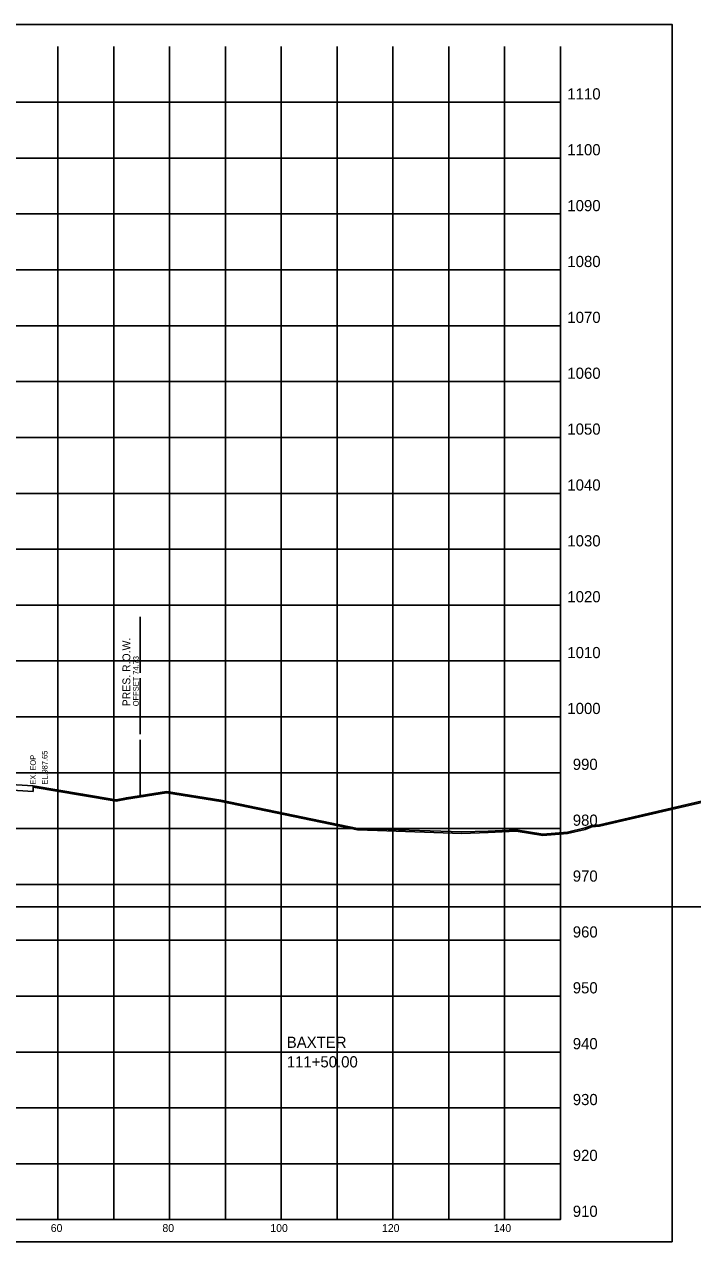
# Model space of a CAD drawing. Extents: x 5868 to 6683, y 2883 to 19120.
# Drawn here: x 6247.8 to 6367.5, y 14385.1 to 14603 of the extents above; entities that cross this region are included whole.
import ezdxf

# ---------------------------------------------------------------- set-up
doc = ezdxf.new("R2010")
doc.units = 0
for name, color, linetype in [('DESIGN - SHEET - Corner Text', 7, 'Continuous'), ('DESIGN - SHEET - Light Grid', 7, 'Continuous'), ('DESIGN - SHEET - Linework', 7, 'Continuous'), ('DESIGN - SHEET - Plot Shape', 7, 'Continuous'), ('DESIGN - TYPICAL - Warning Text', 7, 'Continuous'), ('SURVEY - GROUND - Bottom of Topsoil Layer', 7, 'Continuous'), ('SURVEY - GROUND - Existing Pavement Layer', 7, 'Continuous'), ('SURVEY - GROUND - Existing Pavement Text', 7, 'Continuous'), ('SURVEY - GROUND - Top of Ground', 7, 'Continuous'), ('SURVEY - PROPERTY - ROW Lines', 7, 'Continuous'), ('SURVEY - PROPERTY - ROW Lines Text', 7, 'Continuous')]:
    doc.layers.add(name, color=color, linetype=linetype)

msp = doc.modelspace()

# ---------------------------------------------------------------- linework, layer by layer
at = {"layer": 'DESIGN - SHEET - Light Grid'}
msp.add_line((6193.78, 14445.07), (6493.78, 14445.07), dxfattribs=at)
at = {"layer": 'DESIGN - SHEET - Linework'}
for p, q in [((6253.78, 14389.07), (6253.78, 14599.07)), ((6263.78, 14389.07), (6263.78, 14599.07)), ((6273.78, 14389.07), (6273.78, 14599.07)), ((6283.78, 14389.07), (6283.78, 14599.07)), ((6293.78, 14389.07), (6293.78, 14599.07)), ((6303.78, 14389.07), (6303.78, 14599.07)), ((6313.78, 14389.07), (6313.78, 14599.07)), ((6323.78, 14389.07), (6323.78, 14599.07)), ((6333.78, 14389.07), (6333.78, 14599.07)), ((6043.78, 14589.07), (6343.78, 14589.07)), ((6043.78, 14579.07), (6343.78, 14579.07)), ((6043.78, 14569.07), (6343.78, 14569.07)), ((6043.78, 14559.07), (6343.78, 14559.07)), ((6043.78, 14549.07), (6343.78, 14549.07)), ((6043.78, 14539.07), (6343.78, 14539.07)), ((6043.78, 14529.07), (6343.78, 14529.07)), ((6043.78, 14519.07), (6343.78, 14519.07)), ((6043.78, 14509.07), (6343.78, 14509.07)), ((6043.78, 14499.07), (6343.78, 14499.07)), ((6043.78, 14489.07), (6343.78, 14489.07)), ((6043.78, 14479.07), (6343.78, 14479.07)), ((6043.78, 14469.07), (6343.78, 14469.07)), ((6043.78, 14459.07), (6343.78, 14459.07)), ((6043.78, 14449.07), (6343.78, 14449.07)), ((6043.78, 14439.07), (6343.78, 14439.07)), ((6043.78, 14429.07), (6343.78, 14429.07)), ((6043.78, 14419.07), (6343.78, 14419.07)), ((6043.78, 14409.07), (6343.78, 14409.07)), ((6043.78, 14399.07), (6343.78, 14399.07))]:
    msp.add_line(p, q, dxfattribs=at)
msp.add_lwpolyline([(6043.78, 14599.07), (6043.78, 14389.07), (6343.78, 14389.07), (6343.78, 14599.07)], dxfattribs=at)
at = {"layer": 'DESIGN - SHEET - Plot Shape'}
msp.add_lwpolyline([(6023.78, 14603.01), (6363.78, 14603.01), (6363.78, 14385.13), (6023.78, 14385.13)], close=True, dxfattribs=at)
at = {"layer": 'SURVEY - GROUND - Bottom of Topsoil Layer'}
for p, q in [((6249.34, 14466.47), (6249.34, 14466.72)), ((6249.34, 14466.47), (6258.2, 14465)), ((6266.05, 14464.33), (6273.23, 14465.44)), ((6273.23, 14465.44), (6282.95, 14463.93)), ((6350.78, 14459.47), (6382.86, 14466.94)), ((6258.2, 14465), (6264.2, 14463.99)), ((6264.2, 14463.99), (6266.05, 14464.33)), ((6282.95, 14463.93), (6307.44, 14458.83)), ((6307.44, 14458.83), (6311.02, 14458.7)), ((6311.02, 14458.7), (6326.11, 14458.21)), ((6330.82, 14458.34), (6335.86, 14458.61)), ((6335.86, 14458.61), (6340.63, 14457.81)), ((6345.06, 14458.16), (6348.21, 14458.93)), ((6348.21, 14458.93), (6349.44, 14459.35)), ((6349.44, 14459.35), (6350.78, 14459.47)), ((6326.11, 14458.21), (6330.82, 14458.34)), ((6340.63, 14457.81), (6345.06, 14458.16))]:
    msp.add_line(p, q, dxfattribs=at)
at = {"layer": 'SURVEY - GROUND - Existing Pavement Layer'}
for p in [(6235.31, 14466.54), (6249.34, 14466.72)]:
    msp.add_line(p, (6249.34, 14465.72), dxfattribs=at)
at = {"layer": 'SURVEY - GROUND - Top of Ground'}
msp.add_lwpolyline([(6235.31, 14467.54), (6249.34, 14466.72), (6258.2, 14465.25), (6264.2, 14464.24), (6266.05, 14464.58), (6273.23, 14465.69), (6282.95, 14464.18), (6307.44, 14459.08), (6311.02, 14458.95), (6326.11, 14458.46), (6330.82, 14458.59), (6335.86, 14458.86), (6340.63, 14458.06), (6345.06, 14458.41), (6348.21, 14459.18), (6349.44, 14459.6), (6350.78, 14459.72), (6382.86, 14467.19)], dxfattribs=at)
at = {"layer": 'SURVEY - PROPERTY - ROW Lines'}
for p, q in [((6268.51, 14486.96), (6268.51, 14496.96)), ((6268.51, 14475.96), (6268.51, 14485.96)), ((6268.51, 14464.96), (6268.51, 14474.96))]:
    msp.add_line(p, q, dxfattribs=at)

# ---------------------------------------------------------------- texts
at = {"layer": 'DESIGN - SHEET - Corner Text'}
for s, height, p in [('1110', 2, (6345.03, 14589.57)), ('1100', 2, (6345.03, 14579.57)), ('1090', 2, (6345.03, 14569.57)), ('1080', 2, (6345.03, 14559.57)), ('1070', 2, (6345.03, 14549.57)), ('1060', 2, (6345.03, 14539.57)), ('1050', 2, (6345.03, 14529.57)), ('1040', 2, (6345.03, 14519.57)), ('1030', 2, (6345.03, 14509.57)), ('1020', 2, (6345.03, 14499.57)), ('1010', 2, (6345.03, 14489.57)), ('1000', 2, (6345.03, 14479.57)), ('990', 2, (6346, 14469.57)), ('980', 2, (6346, 14459.57)), ('970', 2, (6346, 14449.57)), ('960', 2, (6346, 14439.57)), ('950', 2, (6346, 14429.57)), ('940', 2, (6346, 14419.57)), ('930', 2, (6346, 14409.57)), ('920', 2, (6346, 14399.57)), ('910', 2, (6346, 14389.57)), ('60', 1.4, (6252.52, 14386.87)), ('80', 1.4, (6272.52, 14386.87)), ('100', 1.4, (6291.84, 14386.87)), ('120', 1.4, (6311.84, 14386.87)), ('140', 1.4, (6331.84, 14386.87))]:
    msp.add_text(s, height=height, dxfattribs=at).set_placement(p)
at = {"layer": 'DESIGN - TYPICAL - Warning Text'}
for s, p in [('BAXTER', (6294.78, 14419.82)), ('111+50.00', (6294.78, 14416.32))]:
    msp.add_text(s, height=2, dxfattribs=at).set_placement(p)
at = {"layer": 'SURVEY - GROUND - Existing Pavement Text'}
for s, p in [('EX. EOP', (6249.84, 14466.92)), ('EL.987.65', (6251.93, 14466.92))]:
    msp.add_text(s, height=1, rotation=90, dxfattribs=at).set_placement(p)
at = {"layer": 'SURVEY - PROPERTY - ROW Lines Text'}
for s, height, p in [('PRES. R.O.W.', 1.4, (6266.76, 14480.96)), ('OFFSET 74.73', 1, (6268.26, 14480.96))]:
    msp.add_text(s, height=height, rotation=90, dxfattribs=at).set_placement(p)

doc.saveas('drawing.dxf')
